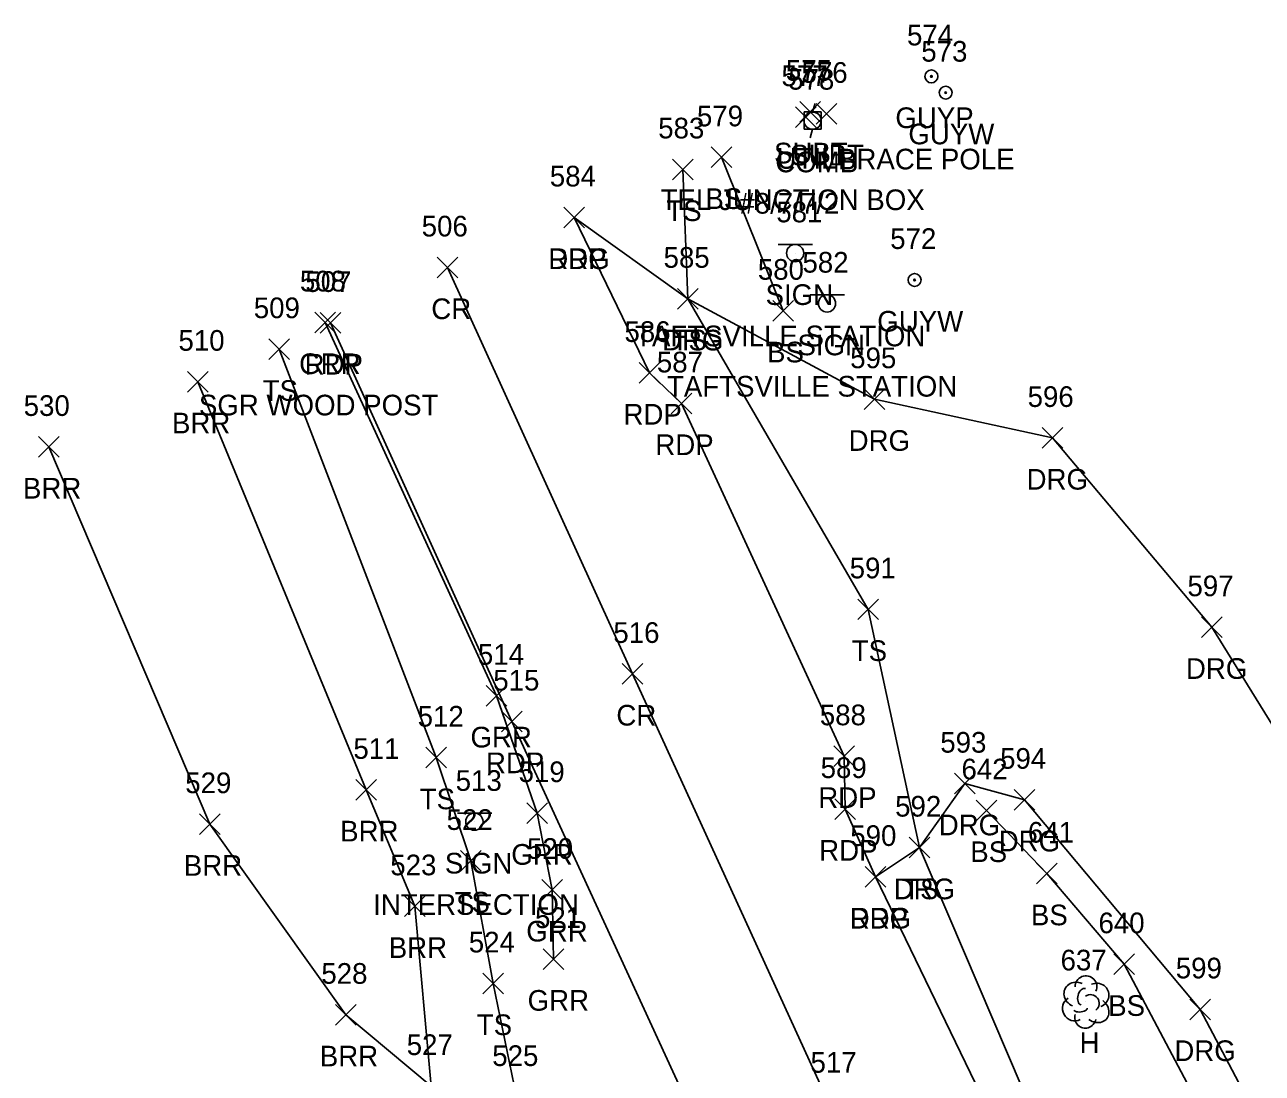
# Model space of a CAD drawing. Extents: x 1647133 to 1649138, y 411736 to 414924.
# Drawn here: x 1648482.9 to 1648602.7, y 412350.2 to 412451.7 of the extents above; entities that cross this region are included whole.
import ezdxf

# ---------------------------------------------------------------- set-up
doc = ezdxf.new("R2010")
doc.units = 0
for name, color, linetype in [('L_A', 7, 'Continuous'), ('L_I', 7, 'Continuous'), ('L_TIC', 7, 'Continuous'), ('LABL', 7, 'Continuous'), ('LELB', 7, 'Continuous'), ('LTD', 7, 'Continuous'), ('P_A', 7, 'Continuous'), ('P_I', 7, 'Continuous'), ('P_TIC', 7, 'Continuous'), ('PET', 7, 'Continuous'), ('PRC', 7, 'Continuous'), ('R_A', 7, 'Continuous'), ('R_C', 7, 'Continuous'), ('R_I', 7, 'Continuous'), ('R_TIC', 7, 'Continuous'), ('RDG', 7, 'Continuous'), ('RGR', 7, 'Continuous'), ('S_A', 7, 'Continuous'), ('S_C', 7, 'Continuous'), ('S_I', 7, 'Continuous'), ('SSGN', 7, 'Continuous'), ('U_A', 7, 'Continuous'), ('U_C', 7, 'Continuous'), ('U_I', 7, 'Continuous'), ('U_TIC', 7, 'Continuous'), ('UDEFAULT', 7, 'Continuous'), ('UP', 7, 'Continuous'), ('UPGW', 7, 'Continuous')]:
    doc.layers.add(name, color=color, linetype=linetype)

msp = doc.modelspace()

# ---------------------------------------------------------------- linework, layer by layer
at = {"layer": 'L_TIC'}
for points in [[(1648549.37, 412437.82), (1648551.37, 412439.82)], [(1648551.37, 412437.82), (1648549.37, 412439.82)], [(1648545.62, 412436.65), (1648547.62, 412438.65)], [(1648547.62, 412436.65), (1648545.62, 412438.65)], [(1648546.13, 412424.13), (1648548.13, 412426.13)], [(1648548.13, 412424.13), (1648546.13, 412426.13)], [(1648555.34, 412422.97), (1648557.34, 412424.97)], [(1648557.34, 412422.97), (1648555.34, 412424.97)], [(1648506.56, 412419.25), (1648508.56, 412421.25)], [(1648508.56, 412419.25), (1648506.56, 412421.25)], [(1648498.71, 412416.1), (1648500.71, 412418.1)], [(1648500.71, 412416.1), (1648498.71, 412418.1)], [(1648484.29, 412409.79), (1648486.29, 412411.79)], [(1648486.29, 412409.79), (1648484.29, 412411.79)], [(1648563.57, 412394.07), (1648565.57, 412396.07)], [(1648565.57, 412394.07), (1648563.57, 412396.07)], [(1648521.76, 412379.72), (1648523.76, 412381.72)], [(1648523.76, 412379.72), (1648521.76, 412381.72)], [(1648514.98, 412376.6), (1648516.98, 412378.6)], [(1648516.98, 412376.6), (1648514.98, 412378.6)], [(1648575.01, 412374.61), (1648577.01, 412376.61)], [(1648577.01, 412374.61), (1648575.01, 412376.61)], [(1648499.85, 412373.28), (1648501.85, 412375.28)], [(1648501.85, 412373.28), (1648499.85, 412375.28)], [(1648568.55, 412371.01), (1648570.55, 412373.01)], [(1648570.55, 412371.01), (1648568.55, 412373.01)], [(1648568.55, 412371.01), (1648570.55, 412373.01)], [(1648570.55, 412371.01), (1648568.55, 412373.01)], [(1648525.13, 412369.72), (1648527.13, 412371.72)], [(1648527.13, 412369.72), (1648525.13, 412371.72)], [(1648580.87, 412368.49), (1648582.87, 412370.49)], [(1648582.87, 412368.49), (1648580.87, 412370.49)], [(1648519.69, 412365.33), (1648521.69, 412367.33)], [(1648521.69, 412365.33), (1648519.69, 412367.33)], [(1648588.36, 412359.72), (1648590.36, 412361.72)], [(1648590.36, 412359.72), (1648588.36, 412361.72)], [(1648527.28, 412357.86), (1648529.28, 412359.86)], [(1648529.28, 412357.86), (1648527.28, 412359.86)], [(1648513.01, 412354.83), (1648515.01, 412356.83)], [(1648515.01, 412354.83), (1648513.01, 412356.83)]]:
    msp.add_lwpolyline(points, dxfattribs=at)
at = {"layer": 'LABL'}
msp.add_lwpolyline([(1648499.71, 412417.1), (1648515.98, 412377.6), (1648520.69, 412366.33), (1648522.28, 412348.93), (1648514.01, 412355.83), (1648500.85, 412374.28), (1648485.29, 412410.79)], dxfattribs=at)
at = {"layer": 'LELB'}
for points in [[(1648550.37, 412438.82), (1648556.34, 412423.97)], [(1648546.62, 412437.65), (1648547.13, 412425.13), (1648564.57, 412395.07), (1648569.55, 412372.01)], [(1648507.56, 412420.25), (1648522.76, 412380.72), (1648526.13, 412370.72), (1648528.28, 412358.86), (1648530.55, 412347.87), (1648527.17, 412339.77), (1648512.56, 412329.21)], [(1648634.6, 412298.08), (1648626.99, 412306.25), (1648617.19, 412313.47), (1648609.83, 412321.13), (1648597.76, 412344.82), (1648589.36, 412360.72), (1648581.87, 412369.49), (1648576.01, 412375.61)], [(1648569.55, 412372.01), (1648582.32, 412342.11), (1648598.27, 412308.65), (1648609.53, 412282.35), (1648621.03, 412259.1), (1648624.78, 412251.33), (1648635.37, 412226.99), (1648645.42, 412206.79), (1648666.11, 412172.04)]]:
    msp.add_lwpolyline(points, dxfattribs=at)
at = {"layer": 'LTD'}
msp.add_line((1648585.6, 412357.12), (1648585.6, 412357.12), dxfattribs=at)
msp.add_line((1648585.6, 412357.12), (1648585.6, 412357.12), dxfattribs=at)
msp.add_arc((1648585.65, 412358.55), 1.05, 335.5272, 180.9563, dxfattribs=at)
for centre, major_axis, ratio, start_param, end_param in [((1648584.81, 412357.78), (1.21, -0.51), 0.895232, 1.570796, 4.712389), ((1648585.39, 412357.58), (-0.208, -0.792), 0.645439, 3.141593, 6.283185), ((1648586.64, 412357.7), (-1.14, -0.48), 0.949671, 1.570796, 4.712389), ((1648584.52, 412356.41), (0.58, -1.04), 0.959034, 3.141593, 6.283185), ((1648586.1, 412356.95), (-0.5, 0.667), 0.989748, 3.141593, 6.283185), ((1648586.6, 412356.28), (-1.09, 0.79), 0.841452, 1.570796, 4.712389), ((1648585.6, 412355.62), (0.26, 1.06), 0.942809, 1.570796, 4.712389), ((1648585.14, 412356.37), (-0.625, -0.083), 0.423636, 0, 3.141593)]:
    msp.add_ellipse(centre, major_axis=major_axis, ratio=ratio, start_param=start_param, end_param=end_param, dxfattribs=at)
at = {"layer": 'P_TIC'}
for points in [[(1648535.12, 412432), (1648537.12, 412434)], [(1648537.12, 412432), (1648535.12, 412434)], [(1648522.86, 412427.16), (1648524.86, 412429.16)], [(1648524.86, 412427.16), (1648522.86, 412429.16)], [(1648511.54, 412421.79), (1648513.54, 412423.79)], [(1648513.54, 412421.79), (1648511.54, 412423.79)], [(1648542.4, 412416.95), (1648544.4, 412418.95)], [(1648544.4, 412416.95), (1648542.4, 412418.95)], [(1648545.49, 412414), (1648547.49, 412416)], [(1648547.49, 412414), (1648545.49, 412416)], [(1648540.76, 412387.82), (1648542.76, 412389.82)], [(1648542.76, 412387.82), (1648540.76, 412389.82)], [(1648529.09, 412383.21), (1648531.09, 412385.21)], [(1648531.09, 412383.21), (1648529.09, 412385.21)], [(1648561.25, 412379.85), (1648563.25, 412381.85)], [(1648563.25, 412379.85), (1648561.25, 412381.85)], [(1648561.34, 412374.74), (1648563.34, 412376.74)], [(1648563.34, 412374.74), (1648561.34, 412376.74)], [(1648564.29, 412368.17), (1648566.29, 412370.17)], [(1648566.29, 412368.17), (1648564.29, 412370.17)]]:
    msp.add_lwpolyline(points, dxfattribs=at)
at = {"layer": 'PET'}
for points in [[(1648536.12, 412433), (1648543.4, 412417.95), (1648546.49, 412415), (1648562.25, 412380.85), (1648562.34, 412375.74), (1648565.29, 412369.17), (1648579.3, 412340.19), (1648594.41, 412306.78), (1648606.35, 412280.64), (1648620.63, 412249.26), (1648631.78, 412225.06), (1648641.27, 412204.57), (1648646.81, 412192.55), (1648664.82, 412155.81), (1648677.43, 412126.91), (1648681.85, 412118.14), (1648693.97, 412097.36), (1648709.51, 412075.41), (1648723.89, 412057.12), (1648746.98, 412031.15), (1648768.7, 412011.08), (1648794.52, 411987.62), (1648826.41, 411959.79)], [(1648512.54, 412422.79), (1648530.09, 412384.21), (1648549.58, 412341.86), (1648567.72, 412302.19), (1648584.89, 412264.91), (1648603.96, 412222.56), (1648616.99, 412192.51), (1648626.59, 412174.02), (1648634.7, 412156.35), (1648647.72, 412129.2), (1648659.19, 412106.44), (1648667.01, 412092.62), (1648674.66, 412079.41), (1648685.66, 412062.52), (1648700.07, 412044.86), (1648717.47, 412025.77), (1648741.25, 412001.12), (1648755.32, 411988.12), (1648772.85, 411971.96)]]:
    msp.add_lwpolyline(points, dxfattribs=at)
at = {"layer": 'PRC'}
msp.add_lwpolyline([(1648523.86, 412428.16), (1648541.76, 412388.82), (1648560.79, 412347.22), (1648578.95, 412307.66), (1648596.52, 412268.85), (1648615.51, 412228.06), (1648629.38, 412198.52), (1648645.41, 412164.54), (1648659.58, 412134.14), (1648672.04, 412110.75), (1648683.9, 412091.11), (1648700.38, 412068.34), (1648715.84, 412049.98), (1648739.6, 412024.91), (1648761.87, 412004.35), (1648787.64, 411981.06), (1648820.99, 411950.62), (1648837.38, 411936.25), (1648865.13, 411910.89), (1648893.84, 411885.62), (1648930.35, 411852.9), (1648951.42, 411834.1), (1648988.1, 411800.42), (1649025.04, 411766.66)], dxfattribs=at)
at = {"layer": 'R_TIC'}
for points in [[(1648535.12, 412432), (1648537.12, 412434)], [(1648537.12, 412432), (1648535.12, 412434)], [(1648546.13, 412424.13), (1648548.13, 412426.13)], [(1648548.13, 412424.13), (1648546.13, 412426.13)], [(1648511.01, 412421.84), (1648513.01, 412423.84)], [(1648513.01, 412421.84), (1648511.01, 412423.84)], [(1648564.19, 412414.41), (1648566.19, 412416.41)], [(1648566.19, 412414.41), (1648564.19, 412416.41)], [(1648581.41, 412410.66), (1648583.41, 412412.66)], [(1648583.41, 412410.66), (1648581.41, 412412.66)], [(1648596.83, 412392.34), (1648598.83, 412394.34)], [(1648598.83, 412392.34), (1648596.83, 412394.34)], [(1648527.59, 412385.7), (1648529.59, 412387.7)], [(1648529.59, 412385.7), (1648527.59, 412387.7)], [(1648572.92, 412377.2), (1648574.92, 412379.2)], [(1648574.92, 412377.2), (1648572.92, 412379.2)], [(1648578.71, 412375.64), (1648580.71, 412377.64)], [(1648580.71, 412375.64), (1648578.71, 412377.64)], [(1648531.54, 412374.35), (1648533.54, 412376.35)], [(1648533.54, 412374.35), (1648531.54, 412376.35)], [(1648568.55, 412371.01), (1648570.55, 412373.01)], [(1648570.55, 412371.01), (1648568.55, 412373.01)], [(1648564.29, 412368.17), (1648566.29, 412370.17)], [(1648566.29, 412368.17), (1648564.29, 412370.17)], [(1648532.99, 412366.92), (1648534.99, 412368.92)], [(1648534.99, 412366.92), (1648532.99, 412368.92)], [(1648533.13, 412360.22), (1648535.13, 412362.22)], [(1648535.13, 412360.22), (1648533.13, 412362.22)], [(1648595.71, 412355.35), (1648597.71, 412357.35)], [(1648597.71, 412355.35), (1648595.71, 412357.35)]]:
    msp.add_lwpolyline(points, dxfattribs=at)
at = {"layer": 'RDG'}
for points in [[(1648536.12, 412433), (1648547.13, 412425.13), (1648565.19, 412415.41), (1648582.41, 412411.66), (1648597.83, 412393.34), (1648613.48, 412368.05), (1648631.94, 412343.81), (1648651.81, 412314.2), (1648648.53, 412301.45), (1648665.01, 412273.87)], [(1648565.29, 412369.17), (1648569.55, 412372.01), (1648573.92, 412378.2), (1648579.71, 412376.64), (1648596.71, 412356.35), (1648610.62, 412329.91), (1648623.3, 412310.38), (1648639.16, 412296.81), (1648644.94, 412290.35), (1648657.02, 412269.19)]]:
    msp.add_lwpolyline(points, dxfattribs=at)
at = {"layer": 'RGR'}
msp.add_lwpolyline([(1648512.01, 412422.84), (1648528.59, 412386.7), (1648532.54, 412375.35), (1648533.99, 412367.92), (1648534.13, 412361.22)], dxfattribs=at)
at = {"layer": 'SSGN'}
for p, q in [((1648555.85, 412430.38), (1648559.18, 412430.38)), ((1648557.5, 412429.55), (1648557.5, 412429.55)), ((1648558.95, 412425.52), (1648562.28, 412425.52)), ((1648560.59, 412424.68), (1648560.59, 412424.68)), ((1648524.82, 412375.35), (1648528.15, 412375.35)), ((1648526.46, 412374.52), (1648526.46, 412374.52))]:
    msp.add_line(p, q, dxfattribs=at)
for centre in [(1648557.5, 412429.55), (1648560.59, 412424.68), (1648526.46, 412374.52)]:
    msp.add_circle(centre, 0.833, dxfattribs=at)
at = {"layer": 'U_TIC'}
for points in [[(1648557.96, 412442.23), (1648559.96, 412444.23)], [(1648559.96, 412442.23), (1648557.96, 412444.23)], [(1648559.54, 412442.03), (1648561.54, 412444.03)], [(1648561.54, 412442.03), (1648559.54, 412444.03)]]:
    msp.add_lwpolyline(points, dxfattribs=at)
at = {"layer": 'UDEFAULT'}
for points in [[(1648557.55, 412441.71), (1648559.55, 412443.71)], [(1648559.55, 412441.71), (1648557.55, 412443.71)]]:
    msp.add_lwpolyline(points, dxfattribs=at)
at = {"layer": 'UP'}
for p, q in [((1648558.36, 412441.54), (1648558.36, 412443.21)), ((1648558.36, 412443.21), (1648560.03, 412443.21)), ((1648559.44, 412444.04), (1648559.19, 412443.21)), ((1648560.03, 412443.21), (1648560.03, 412441.54)), ((1648559.19, 412442.37), (1648559.19, 412442.37)), ((1648560.03, 412441.54), (1648558.36, 412441.54)), ((1648558.94, 412440.71), (1648559.19, 412441.54))]:
    msp.add_line(p, q, dxfattribs=at)
msp.add_circle((1648559.19, 412442.37), 0.833, dxfattribs=at)
at = {"layer": 'UPGW'}
for centre, radius in [((1648570.69, 412446.65), 0.625), ((1648570.69, 412446.65), 0.0833), ((1648572.07, 412445.08), 0.625), ((1648572.07, 412445.08), 0.0833), ((1648569.06, 412426.95), 0.625), ((1648569.06, 412426.95), 0.0833)]:
    msp.add_circle(centre, radius, dxfattribs=at)

# ---------------------------------------------------------------- texts
at = {"layer": 'L_A'}
for s, p in [('BS', (1648548.81, 412433.82)), ('TS', (1648545.03, 412432.65)), ('TS', (1648545.54, 412420.13)), ('BS', (1648554.78, 412418.97)), ('TS', (1648505.97, 412415.25)), ('BRR', (1648497.19, 412412.1)), ('BRR', (1648482.77, 412405.79)), ('TS', (1648562.98, 412390.07)), ('TS', (1648521.17, 412375.72)), ('BRR', (1648513.47, 412372.6)), ('BS', (1648574.45, 412370.61)), ('BRR', (1648498.34, 412369.28)), ('TS', (1648567.96, 412367.01)), ('TS', (1648567.96, 412367.01)), ('TS', (1648524.54, 412365.72)), ('BS', (1648580.32, 412364.49)), ('BRR', (1648518.17, 412361.33)), ('BS', (1648587.8, 412355.72)), ('TS', (1648526.69, 412353.86)), ('H', (1648585.03, 412352.12)), ('BRR', (1648511.5, 412350.83))]:
    msp.add_text(s, height=2, dxfattribs=at).set_placement(p)
at = {"layer": 'L_I'}
for s, p in [('579', (1648548, 412441.82)), ('583', (1648544.25, 412440.65)), ('585', (1648544.77, 412428.13)), ('580', (1648553.89, 412426.97)), ('509', (1648505.11, 412423.25)), ('510', (1648497.82, 412420.1)), ('530', (1648482.84, 412413.79)), ('591', (1648562.78, 412398.07)), ('512', (1648520.97, 412383.72)), ('511', (1648514.75, 412380.6)), ('642', (1648573.6, 412378.61)), ('529', (1648498.48, 412377.28)), ('592', (1648567.18, 412375.01)), ('592', (1648567.18, 412375.01)), ('522', (1648523.77, 412373.72)), ('641', (1648580.03, 412372.49)), ('523', (1648518.32, 412369.33)), ('640', (1648586.86, 412363.72)), ('524', (1648525.92, 412361.86)), ('637', (1648583.19, 412360.12)), ('528', (1648511.65, 412358.83)), ('527', (1648519.91, 412351.93)), ('525', (1648528.19, 412350.87))]:
    msp.add_text(s, height=2, dxfattribs=at).set_placement(p)
at = {"layer": 'P_A'}
for s, p in [('RDP', (1648533.61, 412428)), ('CR', (1648522.29, 412423.16)), ('RDP', (1648510.03, 412417.79)), ('RDP', (1648540.89, 412412.95)), ('RDP', (1648543.97, 412410)), ('CR', (1648540.2, 412383.82)), ('RDP', (1648527.58, 412379.21)), ('RDP', (1648559.74, 412375.85)), ('RDP', (1648559.83, 412370.74)), ('RDP', (1648562.78, 412364.17))]:
    msp.add_text(s, height=2, dxfattribs=at).set_placement(p)
at = {"layer": 'P_I'}
for s, p in [('584', (1648533.76, 412436)), ('506', (1648521.36, 412431.16)), ('507', (1648510.1, 412425.79)), ('586', (1648540.98, 412420.95)), ('587', (1648544.12, 412418)), ('516', (1648539.91, 412391.82)), ('515', (1648528.29, 412387.21)), ('588', (1648559.89, 412383.85)), ('589', (1648559.97, 412378.74)), ('590', (1648562.84, 412372.17)), ('517', (1648558.99, 412350.22))]:
    msp.add_text(s, height=2, dxfattribs=at).set_placement(p)
at = {"layer": 'R_A'}
for s, p in [('DRG', (1648533.61, 412428)), ('DRG', (1648544.62, 412420.13)), ('GRR', (1648509.5, 412417.84)), ('DRG', (1648562.68, 412410.41)), ('DRG', (1648579.9, 412406.66)), ('DRG', (1648595.32, 412388.34)), ('GRR', (1648526.08, 412381.7)), ('DRG', (1648571.4, 412373.2)), ('DRG', (1648577.2, 412371.64)), ('GRR', (1648530.03, 412370.35)), ('DRG', (1648567.04, 412367.01)), ('DRG', (1648562.78, 412364.17)), ('GRR', (1648531.48, 412362.92)), ('GRR', (1648531.61, 412356.22)), ('DRG', (1648594.2, 412351.35))]:
    msp.add_text(s, height=2, dxfattribs=at).set_placement(p)
at = {"layer": 'R_C'}
msp.add_text('SGR WOOD POST', height=2, dxfattribs=at).set_placement((1648499.8, 412413.84))
at = {"layer": 'R_I'}
for s, p in [('584', (1648533.76, 412436)), ('585', (1648544.77, 412428.13)), ('508', (1648509.57, 412425.84)), ('595', (1648562.83, 412418.41)), ('596', (1648580, 412414.66)), ('597', (1648595.47, 412396.34)), ('514', (1648526.8, 412389.7)), ('593', (1648571.55, 412381.2)), ('594', (1648577.34, 412379.64)), ('519', (1648530.74, 412378.35)), ('592', (1648567.18, 412375.01)), ('590', (1648562.84, 412372.17)), ('520', (1648531.55, 412370.92)), ('521', (1648532.33, 412364.22)), ('599', (1648594.34, 412359.35))]:
    msp.add_text(s, height=2, dxfattribs=at).set_placement(p)
at = {"layer": 'S_A'}
for p in [(1648554.64, 412424.53), (1648557.73, 412419.66), (1648523.6, 412369.5)]:
    msp.add_text('SIGN', height=2, dxfattribs=at).set_placement(p)
at = {"layer": 'S_C'}
for s, p in [('TAFTSVILLE STATION', (1648542.01, 412420.53)), ('TAFTSVILLE STATION', (1648545.1, 412415.66)), ('INTERSECTION', (1648516.66, 412365.5))]:
    msp.add_text(s, height=2, dxfattribs=at).set_placement(p)
at = {"layer": 'S_I'}
for s, p in [('581', (1648555.68, 412432.53)), ('582', (1648558.21, 412427.66)), ('513', (1648524.65, 412377.5))]:
    msp.add_text(s, height=2, dxfattribs=at).set_placement(p)
at = {"layer": 'U_A'}
for s, p in [('GUYP', (1648567.2, 412441.65)), ('GUYW', (1648568.46, 412440.08)), ('SUBT', (1648555.46, 412438.23)), ('UTIL', (1648555.71, 412437.71)), ('SUBT', (1648557.03, 412438.03)), ('COMB', (1648555.58, 412437.37)), ('GUYW', (1648565.45, 412421.95))]:
    msp.add_text(s, height=2, dxfattribs=at).set_placement(p)
at = {"layer": 'U_C'}
for s, p in [('BRACE POLE', (1648561.65, 412437.65)), ('TEL JUNCTION BOX', (1648544.48, 412433.71)), ('#8/7/7/2', (1648552.11, 412433.37))]:
    msp.add_text(s, height=2, dxfattribs=at).set_placement(p)
at = {"layer": 'U_I'}
for s, p in [('574', (1648568.33, 412449.65)), ('573', (1648569.71, 412448.08)), ('575', (1648556.6, 412446.23)), ('576', (1648558.12, 412446.03)), ('577', (1648556.18, 412445.71)), ('578', (1648556.83, 412445.37)), ('572', (1648566.7, 412429.95))]:
    msp.add_text(s, height=2, dxfattribs=at).set_placement(p)

doc.saveas('drawing.dxf')
